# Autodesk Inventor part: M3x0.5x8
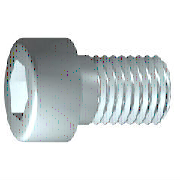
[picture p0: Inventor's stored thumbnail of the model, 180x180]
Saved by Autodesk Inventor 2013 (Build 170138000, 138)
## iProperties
IsCustomPart: 1
Company: 한국ATC센터
Created: 2009-02
Part Number: M3x0.5x8
Material: 강, 연강
Description: 6각머리 태핑 나사
Document SubType Name: Modeling
Standard: KS B 1003
Designer: KYOUNG IL JANG
Standards Organization: KS
Language: ko-KR
Size Designation: M 4 x 12
Categories: <MemberInstance><Categories><Category DisplayName="조임쇠" InternalName="e4da775c-781d-43d5-af7c-5136215cf5a6" Mnemonic="FSTN"><Category DisplayName="볼트" InternalN
Density: 7.86 g/cm^3
Mass: 1.37432 g
Surface Area: 2.584 cm^2
Volume: 0.174849 cm^3
Vendor: CBT Solutions
Author: KYOUNG IL JANG
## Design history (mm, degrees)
sketch "스케치1"
  geometry: L1 (-0.867, 0)-(16, 0); L2 (16, 0)-(16, 1.5); L3 (16, 1.5)-(1.25, 1.5); L4 (1.25, 1.5)-(0.943, 1.5); L5 (0.943, 1.5)-(0, 1.5); L6 (0, 1.5)-(0, 2.75); L7 (0, 2.75)-(-3, 2.75); L8 (-3, 2.75)-(-3, 1.443); L9 (-3, 1.443)-(-1.7, 1.443); L10 (-1.7, 1.443)-(-0.867, 0); L11 (-6.8, 0)-(19.8, 0) reference; L12 (0, -0.55)-(0, 3.3) reference; L13 (1.25, 1.5)-(0, 1.5)
  constraints: 22 end point, 6 parallel, 2 collinear, 2 perpendicular, 1 horizontal, 1 point on line
  dimensions: "d1" = 14.75 distance from line of L3.end L2 (= GEL); "d2" = 0.30683 distance of L4.end L3.end (computed from GAL); "d3" = 3 distance between parallel lines of L8 L6 (= KOH); "d4" = 1.3 distance of L8.end L9.end (= INTI); "d5" = 60 deg angle of L10 L1; "d6" = 3 diameter of L3 L1 (= GD); "d7" = 3 diameter of L5 L1 (= BDM); "d8" = 2.88675 diameter of L9 L1 (= 1.1547 x SW); "d9" = 5.5 diameter of L7 L1 (= KOD); "d26" = 16 distance between parallel lines of L12 L2 (= NLG)
revolve "본체" sketch "스케치1" stored, may be unused: angle "d10" = 90 deg
sketch "스케치2"
  geometry: L1 (0, -3.85)-(0, 3.85) reference; L2 (-3.85, 0)-(3.85, 0) reference; L3 (1.443, 0)-(0.722, -1.25); L4 (0.722, -1.25)-(-0.722, -1.25); L5 (-0.722, -1.25)-(-1.443, 0); L6 (-1.443, 0)-(-0.722, 1.25); L7 (-0.722, 1.25)-(0.722, 1.25); L8 (0.722, 1.25)-(1.443, 0); 2 further points
  constraints: 12 end point, 1 coincident, 1 horizontal alignment, 1 point on line, 12 other
extrude "슬롯" join sketch "스케치2" stored distance "d11" = 10; taper "d12" = 0 deg
workplane "Work Plane1"
fillet "Fillet2" dims "d30" = 0.1 (= R)
body "Solid1"
fillet "모깎기1" dims "d17" = 0.3 (= RR)
feature "스레드" dims "d13" = 14.75 (= GEL), "d14" = 0
chamfer "모따기1" distance "d15" = 0.30673 (= -0.5 x SPD + 0.5 x GD); stored, may be unused: second distance "d16" = 0.30673 (= GUL), angle "d27" = 45 deg
other parameters: "GD" = 3 (= NND) [user parameter; used in 2 equation terms], "NLG" = 16 [user parameter; used in 1 equation term], "GEL" = 14.75 [user parameter; used in 2 equation terms], "KOD" = 5.5 [user parameter; used in 1 equation term], "KOH" = 3 [user parameter; used in 1 equation term], "INTI" = 1.3 [user parameter; used in 1 equation term], "GAL" = 0.30673 (= 0.61345 x PTC) [user parameter; used in 1 equation term], "GUL" = 0.30673 (= 0.61345 x PTC) [user parameter; used in 1 equation term], "BDM" = 3 (= NND) [user parameter; used in 1 equation term], "SW" = 2.5 [user parameter; used in 2 equation terms], "RR" = 0.3 [user parameter; used in 1 equation term], "SPD" = 2.38655 (= NND - 1.2269 x PTC) [user parameter; used in 1 equation term], "d19" = 0, "d28" = 0, "d29" = 0, "R" = 0.1 [user parameter; used in 1 equation term], "PHH" = 0.1 [user parameter], "GD1" = 2.38655 (= THREADDIA - 1.2269 x PTC) [user parameter], "THREADDIA" = 3 [user parameter; used in 1 equation term], "FAWI" = 45 deg [user parameter], "PTC" = 0.5 [user parameter; used in 5 equation terms], "NND" = 3 [user parameter; used in 3 equation terms], "TOA" = 30 deg [user parameter], "E0" = 2.8875 (= 1.155 x SW) [user parameter]
